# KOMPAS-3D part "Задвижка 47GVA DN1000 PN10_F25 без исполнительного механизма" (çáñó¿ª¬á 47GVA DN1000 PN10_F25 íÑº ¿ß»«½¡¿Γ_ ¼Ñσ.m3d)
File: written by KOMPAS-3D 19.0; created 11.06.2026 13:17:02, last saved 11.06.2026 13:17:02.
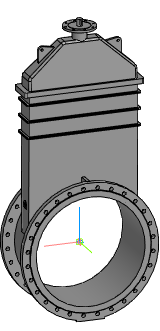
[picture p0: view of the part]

Document properties: Автор: Евгений; Полное имя файла: Z:\3.Личные\kachalov\001_3d для проектировщиков\2.2 Тип 47GVA, 47GVA.Z\_stp\_stp_Задвижка 47GVA DN40-DN1000 без исп.мех\Задвижка 47GVA DN1000 PN10_F25 без исполнит_ мех.m3d

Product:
- Part/product: Задвижка 47GVA DN1000 PN10_F25 без исполнительного механизма

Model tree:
1. Операция без истории:1  (labels: Задвижка 47GVA DN1000 PN10_F25 без исполнительного механизма)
